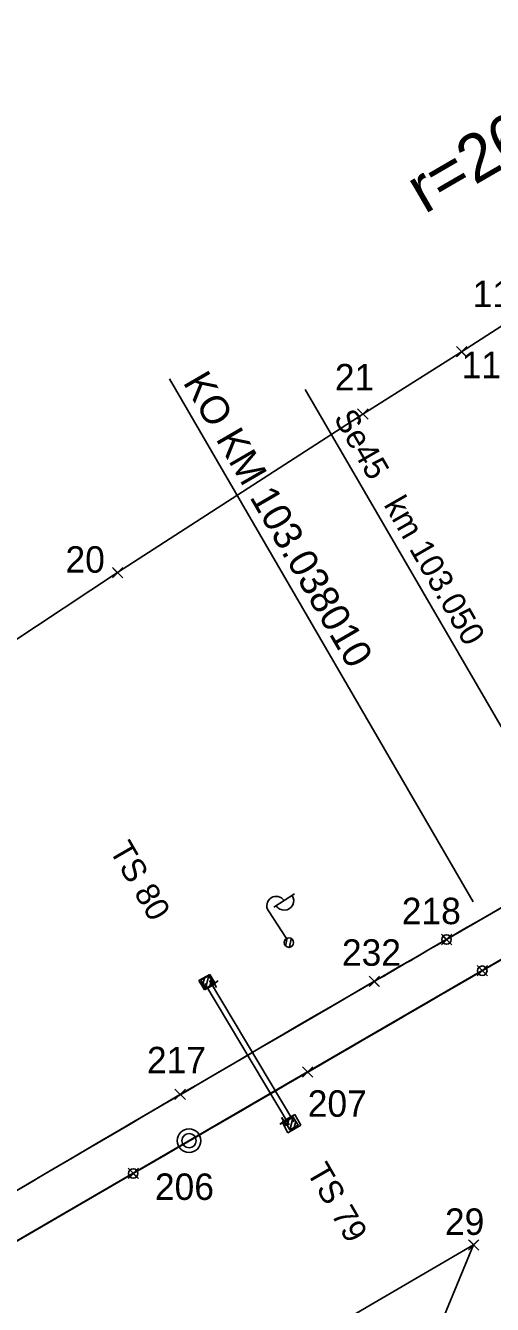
# Model space of a CAD drawing. Extents: x -566182 to -565305, y -1203073 to -1202401.
# Drawn here: x -565870.4 to -565821, y -1202826.9 to -1202691.6 of the extents above; entities that cross this region are included whole.
import ezdxf

# ---------------------------------------------------------------- set-up
doc = ezdxf.new("R2010")
doc.units = 0
for name, color, linetype in [('CD', 7, 'Continuous'), ('LÁTAL_SVRŠEK', 7, 'Continuous'), ('SZDC', 7, 'Continuous'), ('Vrstva 10', 7, 'Continuous'), ('Vrstva 12', 7, 'Continuous'), ('Vrstva 13', 7, 'Continuous'), ('Vrstva 25', 7, 'Continuous'), ('Vrstva 39', 7, 'Continuous'), ('Vrstva 6', 7, 'Continuous'), ('Vrstva 60', 7, 'Continuous')]:
    doc.layers.add(name, color=color, linetype=linetype)

# ---------------------------------------------------------------- blocks, each defined once
blk = doc.blocks.new('C512')
at = {"layer": 'Vrstva 6'}
for radius in [12.5, 7.52]:
    blk.add_circle((0, 0), radius, dxfattribs=at)
blk = doc.blocks.new('C691')
at = {"layer": 'Vrstva 12'}
for p, q in [((-5, 0), (5, 0)), ((0, 5), (0, -5))]:
    blk.add_line(p, q, dxfattribs=at)
blk = doc.blocks.new('C669')
at = {"layer": 'Vrstva 6'}
for p, q in [((0, 5), (0, 40)), ((7, 40), (33, 40)), ((-5, -1), (1, 5)), ((-2, -4), (4, 2))]:
    blk.add_line(p, q, dxfattribs=at)
blk.add_circle((0, 0), 5, dxfattribs=at)
blk.add_circle((0, 0), 5, dxfattribs=at)
for centre, start, end in [((10, 40), 0.0001, 180.0001), ((20, 39.9), 179.2975, 0.7026)]:
    blk.add_arc(centre, 10, start, end, dxfattribs=at)
blk = doc.blocks.new('C661_3')
at = {"layer": 'Vrstva 12'}
for p, q in [((-5, 0.3), (-0.3, 5)), ((-5, -5), (5, 5)), ((0.3, -5), (5, -0.3))]:
    blk.add_line(p, q, dxfattribs=at)
blk.add_lwpolyline([(-5, 5), (5, 5), (5, -5), (-5, -5)], close=True, dxfattribs=at)
blk.add_lwpolyline([(-5, 5), (5, 5), (5, -5), (-5, -5), (-5, 5)], dxfattribs=at)
blk = doc.blocks.new('C661')
at = {"layer": 'Vrstva 12'}
for p, q in [((-5, 0.3), (-0.3, 5)), ((-5, -5), (5, 5)), ((0.3, -5), (5, -0.3))]:
    blk.add_line(p, q, dxfattribs=at)
blk.add_lwpolyline([(-5, 5), (5, 5), (5, -5), (-5, -5)], close=True, dxfattribs=at)
blk.add_lwpolyline([(-5, 5), (5, 5), (5, -5), (-5, -5), (-5, 5)], dxfattribs=at)

msp = doc.modelspace()

# ---------------------------------------------------------------- linework, layer by layer
at = {"layer": 'CD'}
for p, q in [((-565824.28, -1202726.13), (-565816.76, -1202721.27)), ((-565834.73, -1202732.72), (-565824.28, -1202726.13))]:
    msp.add_line(p, q, dxfattribs=at)
at = {"layer": 'LÁTAL_SVRŠEK'}
for p, q in [((-565784.46, -1202769.78), (-565822.09, -1202791.63)), ((-565825.87, -1202788.33), (-565809.12, -1202778.61)), ((-565809.12, -1202778.61), (-565825.87, -1202788.33)), ((-565900.69, -1202837.33), (-565859.02, -1202813.09)), ((-565900.69, -1202837.33), (-565859.02, -1202813.09))]:
    msp.add_line(p, q, dxfattribs=at)
for centre in [(-565825.87, -1202788.33), (-565822.09, -1202791.63), (-565859.02, -1202813.09)]:
    msp.add_circle(centre, 0.5, dxfattribs=at)
for centre, radius, start, end in [((-560804.84, -1211436.41), 10000, 120.139217, 120.189547), ((-540716.95, -1246032.03), 50000, 120.139219, 120.188159), ((-560804.84, -1211436.41), 10000, 120.189547, 120.512837)]:
    msp.add_arc(centre, radius, start, end, dxfattribs=at)
at = {"layer": 'SZDC'}
for points in [[(-566109.86, -1202908.94), (-566097.96, -1202902.03), (-566084.51, -1202894.21), (-566065.16, -1202881.19), (-566062.89, -1202879.66), (-566050.93, -1202871.86), (-566034.12, -1202860.89), (-566014.69, -1202848.22), (-565999.33, -1202838.2), (-565981.56, -1202826.61), (-565964.56, -1202815.52), (-565946.25, -1202803.07), (-565943.74, -1202801.57), (-565935.57, -1202796.69), (-565927.13, -1202791.65), (-565924.54, -1202790.1), (-565905.03, -1202778.89), (-565894.6, -1202771.96), (-565883.49, -1202764.57), (-565860.68, -1202749.5), (-565834.73, -1202732.72)], [(-565859.38, -1202962.26), (-565861.03, -1202936.37), (-565855.35, -1202900.62), (-565842.42, -1202864.28), (-565828.48, -1202833.86), (-565823.01, -1202820.65), (-565873.65, -1202850.2), (-565871.3, -1202853.81), (-565871.36, -1202856.88), (-565872.74, -1202857.66), (-566063.99, -1202965.17)]]:
    msp.add_lwpolyline(points, dxfattribs=at)
at = {"layer": 'Vrstva 10'}
for p, q in [((-565852.07, -1202792.67), (-565850.93, -1202792.02)), ((-565850.93, -1202792.02), (-565850.32, -1202793.01)), ((-565851.48, -1202793.67), (-565852.07, -1202792.67)), ((-565850.32, -1202793.01), (-565851.48, -1202793.67)), ((-565843.28, -1202807.64), (-565841.92, -1202806.85)), ((-565841.92, -1202806.85), (-565841.29, -1202807.97)), ((-565842.65, -1202808.79), (-565843.28, -1202807.64)), ((-565841.29, -1202807.97), (-565842.65, -1202808.79))]:
    msp.add_line(p, q, dxfattribs=at)
at = {"layer": 'Vrstva 12'}
for points in [[(-565851.46, -1202792.98), (-565842.53, -1202807.95)], [(-565850.95, -1202792.67), (-565842.02, -1202807.64)]]:
    msp.add_lwpolyline(points, dxfattribs=at)
at = {"layer": 'Vrstva 6'}
for points in [[(-566068.74, -1202934.92), (-566067.2, -1202934.01), (-566009.26, -1202900.35), (-565952.55, -1202867.42), (-565900.78, -1202837.32), (-565844.77, -1202804.78), (-565792.03, -1202774.14)], [(-565822.19, -1202786.16), (-565810.72, -1202779.5), (-565809.18, -1202778.6)]]:
    msp.add_lwpolyline(points, dxfattribs=at)
msp.add_arc((-561050.64, -1211005.49), 9503.95, 120.13635, 120.525886, dxfattribs=at)
at = {"layer": 'Vrstva 60'}
for p, q in [((-565823.83, -1202726.58), (-565824.83, -1202725.58)), ((-565823.83, -1202725.68), (-565824.83, -1202726.68)), ((-565824.73, -1202726.58), (-565823.73, -1202725.58)), ((-565824.73, -1202725.68), (-565823.73, -1202726.68)), ((-565824.28, -1202726.13), (-565824.28, -1202726.13)), ((-565823.04, -1202784.35), (-565855.18, -1202729)), ((-565840.83, -1202730.11), (-565810.7, -1202782)), ((-565834.28, -1202733.17), (-565835.28, -1202732.17)), ((-565834.28, -1202732.27), (-565835.28, -1202733.27)), ((-565835.18, -1202733.17), (-565834.18, -1202732.17)), ((-565835.18, -1202732.27), (-565834.18, -1202733.27)), ((-565834.73, -1202732.72), (-565834.73, -1202732.72)), ((-565860.23, -1202749.95), (-565861.23, -1202748.95)), ((-565860.23, -1202749.05), (-565861.23, -1202750.05)), ((-565861.13, -1202749.95), (-565860.13, -1202748.95)), ((-565861.13, -1202749.05), (-565860.13, -1202750.05)), ((-565860.68, -1202749.5), (-565860.68, -1202749.5)), ((-565825.42, -1202788.78), (-565826.42, -1202787.78)), ((-565825.42, -1202787.89), (-565826.42, -1202788.89)), ((-565826.32, -1202788.78), (-565825.32, -1202787.78)), ((-565826.32, -1202787.89), (-565825.32, -1202788.89)), ((-565825.87, -1202788.33), (-565825.87, -1202788.33)), ((-565821.64, -1202792.08), (-565822.64, -1202791.08)), ((-565821.64, -1202791.18), (-565822.64, -1202792.18)), ((-565822.54, -1202792.08), (-565821.54, -1202791.08)), ((-565822.54, -1202791.18), (-565821.54, -1202792.18)), ((-565822.09, -1202791.63), (-565822.09, -1202791.63)), ((-565833.06, -1202793.22), (-565834.06, -1202792.22)), ((-565833.06, -1202792.32), (-565834.06, -1202793.32)), ((-565833.95, -1202793.22), (-565832.95, -1202792.22)), ((-565833.95, -1202792.32), (-565832.95, -1202793.32)), ((-565833.51, -1202792.77), (-565833.51, -1202792.77)), ((-565840.11, -1202802.8), (-565841.11, -1202801.8)), ((-565840.11, -1202801.9), (-565841.11, -1202802.9)), ((-565841.01, -1202802.8), (-565840.01, -1202801.8)), ((-565841.01, -1202801.9), (-565840.01, -1202802.9)), ((-565840.56, -1202802.35), (-565840.56, -1202802.35)), ((-565853.61, -1202805.16), (-565854.61, -1202804.16)), ((-565853.61, -1202804.26), (-565854.61, -1202805.26)), ((-565854.51, -1202805.16), (-565853.51, -1202804.16)), ((-565854.51, -1202804.26), (-565853.51, -1202805.26)), ((-565854.06, -1202804.71), (-565854.06, -1202804.71)), ((-565858.57, -1202813.54), (-565859.57, -1202812.54)), ((-565858.57, -1202812.64), (-565859.57, -1202813.64)), ((-565859.47, -1202813.54), (-565858.47, -1202812.54)), ((-565859.47, -1202812.64), (-565858.47, -1202813.64)), ((-565859.02, -1202813.09), (-565859.02, -1202813.09)), ((-565822.56, -1202821.1), (-565823.56, -1202820.1)), ((-565822.56, -1202820.2), (-565823.56, -1202821.2)), ((-565823.46, -1202821.1), (-565822.46, -1202820.1)), ((-565823.46, -1202820.2), (-565822.46, -1202821.2)), ((-565823.01, -1202820.65), (-565823.01, -1202820.65))]:
    msp.add_line(p, q, dxfattribs=at)

# ---------------------------------------------------------------- block references
at = {"layer": 'Vrstva 12'}
for name, p, xscale, yscale, rotation in [('C661_3', (-565851.2, -1202792.83), 0.10000002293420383, 0.10000002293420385, 29.430131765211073), ('C691', (-565850.46, -1202792.97), 0.09999990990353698, 0.09999990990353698, 30.000029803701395), ('C691', (-565843.07, -1202807.61), 0.09999990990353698, 0.09999990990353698, 30.000029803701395), ('C691', (-565843.06, -1202807.61), 0.09999990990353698, 0.09999990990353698, 30.000029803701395), ('C661', (-565842.27, -1202807.8), 0.09999979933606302, 0.09999979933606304, 30.08359134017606)]:
    msp.add_blockref(name, p, dxfattribs=dict(at, xscale=xscale, yscale=yscale, rotation=rotation))
at = {"layer": 'Vrstva 6'}
for name, p, xscale, yscale, rotation in [('C669', (-565842.55, -1202788.66), 0.10000003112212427, 0.10000003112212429, 32.99994277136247), ('C512', (-565853.12, -1202809.62), 0.1, 0.10000000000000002, 180)]:
    msp.add_blockref(name, p, dxfattribs=dict(at, xscale=xscale, yscale=yscale, rotation=rotation))

# ---------------------------------------------------------------- texts
at = {"layer": 'Vrstva 13'}
for s, p in [('TS 80', (-565861.6, -1202778.85)), ('TS 79', (-565840.74, -1202812.9))]:
    msp.add_text(s, height=2.5, rotation=300, dxfattribs=at).set_placement(p)
at = {"layer": 'Vrstva 25'}
msp.add_text('Se45   km 103.050', height=2.5, rotation=299.9873, dxfattribs=at).set_placement((-565837.87, -1202733.13))
at = {"layer": 'Vrstva 39'}
for s, height, rotation, p in [('r=266000m', 5, 30.149, (-565828.2, -1202711.6)), ('KO KM 103.038010', 3, 300.145, (-565853.82, -1202729.36))]:
    msp.add_text(s, height=height, rotation=rotation, dxfattribs=at).set_placement(p)
at = {"layer": 'Vrstva 60'}
for s, p in [('119', (-565823.12, -1202721.4)), ('111', (-565824.28, -1202728.93)), ('21', (-565837.69, -1202730.22)), ('20', (-565866.19, -1202749.51)), ('218', (-565830.61, -1202786.71)), ('232', (-565836.94, -1202791.11)), ('217', (-565857.57, -1202802.49)), ('207', (-565840.56, -1202807.09)), ('206', (-565856.73, -1202815.89)), ('29', (-565826.04, -1202819.59))]:
    msp.add_text(s, height=2.8, dxfattribs=at).set_placement(p)

doc.saveas('drawing.dxf')
